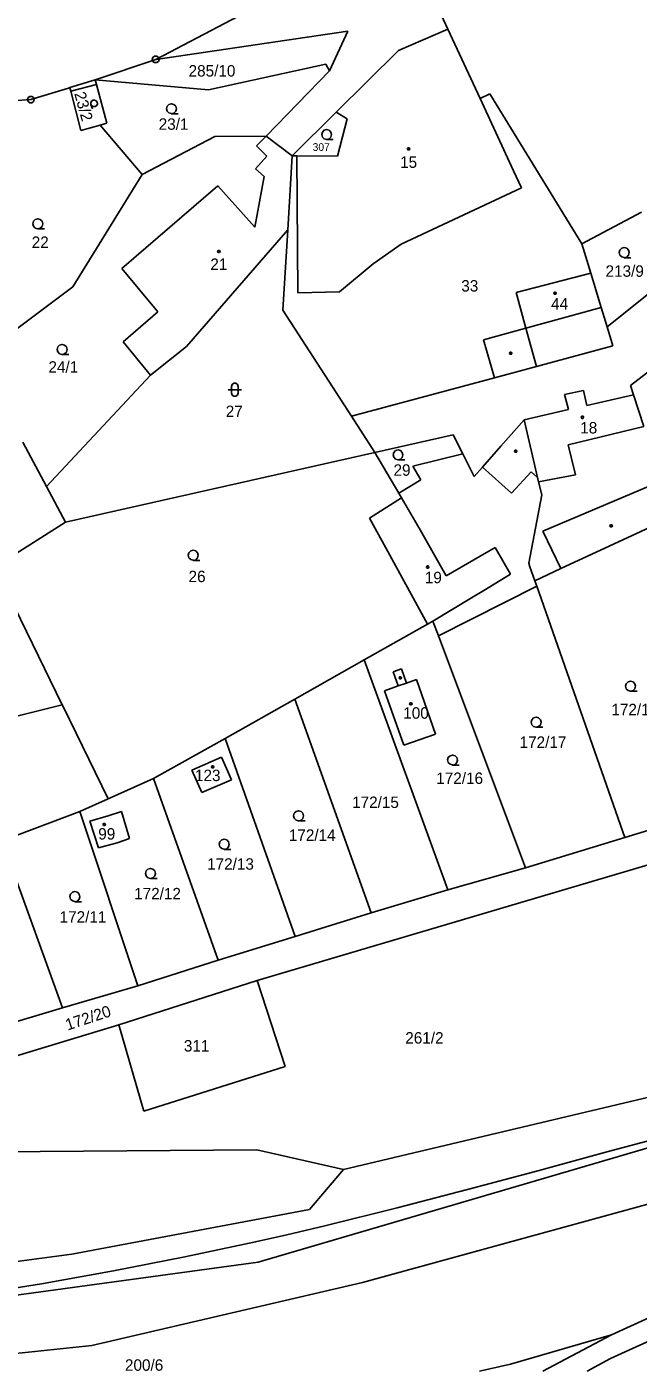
# Model space of a CAD drawing. Extents: x -779723 to -777378, y -1011169 to -1009297.
# Drawn here: x -779077.2 to -778986.4, y -1010479.3 to -1010279.6 of the extents above; entities that cross this region are included whole.
import ezdxf

# ---------------------------------------------------------------- set-up
doc = ezdxf.new("R2010")
doc.units = 0
for name, color, linetype in [('Default', 7, 'Continuous'), ('KN_HRANICE', 7, 'Continuous'), ('KN_KULTURY', 7, 'Continuous'), ('KN_PARCELY', 7, 'Continuous'), ('KN_SLUCKY', 7, 'Continuous'), ('KN_VEDENI', 7, 'Continuous'), ('Železniční svršek', 7, 'Continuous')]:
    doc.layers.add(name, color=color, linetype=linetype)

# ---------------------------------------------------------------- blocks, each defined once
blk = doc.blocks.new('304')
at = {"layer": 'Default'}
blk.add_lwpolyline([(0, 0), (-0.38, 0.1), (-0.65, 0.37), (-0.75, 0.74), (-0.65, 1.11), (-0.38, 1.38), (-0.01, 1.48), (0.36, 1.38), (0.63, 1.11), (0.73, 0.73), (0.63, 0.35), (0.36, 0.08), (-0.02, -0.02), (0.98, -0.02)], dxfattribs=at)
blk = doc.blocks.new('316')
at = {"layer": 'Default'}
for points in [[(-1, 1), (0.27, 1), (1, 1)], [(-0.5, 1.5), (-0.4, 1.79), (-0.15, 1.97), (0.16, 1.97), (0.41, 1.79), (0.51, 1.5), (0.51, 0.5), (0.41, 0.21), (0.16, 0.03), (-0.15, 0.03), (-0.4, 0.21), (-0.5, 0.5), (-0.5, 1.5)]]:
    blk.add_lwpolyline(points, dxfattribs=at)
blk = doc.blocks.new('NAHRADNI_SYMBOL')
at = {"layer": 'Default'}
blk.add_lwpolyline([(0.09, 0.15), (0.18, 0), (0.09, -0.15), (-0.09, -0.15), (-0.18, 0), (-0.09, 0.15), (0.09, 0.15)], dxfattribs=at)
blk = doc.blocks.new('402')
at = {"layer": 'Default'}
blk.add_lwpolyline([(0.09, 0.15), (0.18, 0), (0.09, -0.15), (-0.09, -0.15), (-0.18, 0), (-0.09, 0.15), (0.09, 0.15)], dxfattribs=at)
blk = doc.blocks.new('105')
at = {"layer": 'Default'}
blk.add_line((-0.12, 0), (0.12, 0), dxfattribs=at)
blk.add_lwpolyline([(0.15, 0.48), (0.4, 0.3), (0.5, 0.01), (0.4, -0.28), (0.15, -0.46), (-0.16, -0.46), (-0.41, -0.28), (-0.51, 0.01), (-0.41, 0.3), (-0.16, 0.48), (0.15, 0.48)], dxfattribs=at)

msp = doc.modelspace()

# ---------------------------------------------------------------- linework, layer by layer
at = {"layer": 'KN_HRANICE'}
for p, q in [((-779026.78, -1010253.95), (-779014.69, -1010279.95)), ((-779058.07, -1010284.48), (-779040.66, -1010275.32)), ((-779029.51, -1010280.26), (-779058.07, -1010284.48)), ((-779032.26, -1010286.16), (-779029.51, -1010280.26)), ((-779022.02, -1010283.13), (-779014.69, -1010279.95)), ((-779014.69, -1010279.95), (-779009.89, -1010290.29)), ((-779022.02, -1010283.13), (-779031.26, -1010292.31)), ((-779067.08, -1010287.5), (-779058.07, -1010284.48)), ((-779050.21, -1010289), (-779032.82, -1010285.16)), ((-779032.26, -1010286.16), (-779032.82, -1010285.16)), ((-779041.67, -1010295.86), (-779032.26, -1010286.16)), ((-779071.05, -1010288.72), (-779076.63, -1010290.43)), ((-779070.83, -1010288.65), (-779071.05, -1010288.72)), ((-779067.08, -1010287.5), (-779070.83, -1010288.65)), ((-779070.83, -1010288.65), (-779070.69, -1010289.16)), ((-779069.19, -1010295.01), (-779070.69, -1010289.16)), ((-779066.89, -1010288.17), (-779067.08, -1010287.5)), ((-779067.08, -1010287.5), (-779050.21, -1010289)), ((-779065.31, -1010293.92), (-779066.89, -1010288.17)), ((-779079.33, -1010290.64), (-779076.63, -1010290.43)), ((-779009.89, -1010290.29), (-779008.43, -1010289.59)), ((-779009.89, -1010290.29), (-779004.9, -1010301.02)), ((-778994.79, -1010311.83), (-779008.43, -1010289.59)), ((-779031.26, -1010292.31), (-779037.78, -1010298.79)), ((-779031.26, -1010292.31), (-779029.63, -1010293.31)), ((-779031.09, -1010298.84), (-779029.63, -1010293.31)), ((-779066.34, -1010294.21), (-779069.19, -1010295.01)), ((-779065.31, -1010293.92), (-779066.34, -1010294.21)), ((-779066.34, -1010294.21), (-779060.06, -1010301.54)), ((-779060.06, -1010301.54), (-779049.3, -1010295.9)), ((-779049.3, -1010295.9), (-779041.67, -1010295.86)), ((-779043.09, -1010297.32), (-779041.67, -1010295.86)), ((-779043.09, -1010297.32), (-779041.55, -1010298.82)), ((-779041.67, -1010295.86), (-779037.78, -1010298.79)), ((-779043.27, -1010300.7), (-779041.55, -1010298.82)), ((-779037.78, -1010298.79), (-779038.46, -1010309.75)), ((-779037.78, -1010298.79), (-779037.1, -1010298.8)), ((-779037.1, -1010298.8), (-779031.09, -1010298.84)), ((-779037.1, -1010298.8), (-779036.94, -1010319.12)), ((-779043.27, -1010300.7), (-779041.95, -1010301.84)), ((-779004.9, -1010301.02), (-779003.74, -1010303.52)), ((-779060.06, -1010301.54), (-779070.4, -1010318.23)), ((-779063.1, -1010315.51), (-779048.83, -1010303.23)), ((-779043.36, -1010309.37), (-779048.83, -1010303.23)), ((-779043.36, -1010309.37), (-779041.95, -1010301.84)), ((-779021.61, -1010311.89), (-779003.74, -1010303.52)), ((-778994.79, -1010311.83), (-778985.9, -1010307.16)), ((-779053.49, -1010327.09), (-779038.46, -1010309.75)), ((-779038.46, -1010309.75), (-779039.2, -1010321.7)), ((-779025.76, -1010314.84), (-779021.61, -1010311.89)), ((-778994.79, -1010311.83), (-778993.45, -1010316.22)), ((-779025.76, -1010314.84), (-779030.77, -1010318.99)), ((-779063.1, -1010315.51), (-779057.77, -1010321.93)), ((-779004.53, -1010319.08), (-778993.45, -1010316.22)), ((-778993.45, -1010316.22), (-778991.89, -1010321.33)), ((-778982.17, -1010317.08), (-778991.02, -1010324.17)), ((-779095.54, -1010337.04), (-779070.4, -1010318.23)), ((-779036.94, -1010319.12), (-779030.77, -1010318.99)), ((-779004.53, -1010319.08), (-779003.07, -1010324.38)), ((-779057.77, -1010321.93), (-779062.91, -1010326.41)), ((-779028.99, -1010337.46), (-779039.2, -1010321.7)), ((-778991.89, -1010321.33), (-778991.02, -1010324.17)), ((-779009.39, -1010326.11), (-779003.07, -1010324.38)), ((-778991.02, -1010324.17), (-778990.15, -1010327.02)), ((-779062.91, -1010326.41), (-779058.85, -1010331.38)), ((-779058.85, -1010331.38), (-779053.49, -1010327.09)), ((-779009.39, -1010326.11), (-779007.73, -1010331.75)), ((-779001.5, -1010330.08), (-778990.15, -1010327.02)), ((-779007.73, -1010331.75), (-779001.5, -1010330.08)), ((-778987.54, -1010332.88), (-778983.88, -1010330.06)), ((-779058.85, -1010331.38), (-779074.32, -1010347.9)), ((-779028.99, -1010337.46), (-779007.73, -1010331.75)), ((-778987.54, -1010332.88), (-778987.09, -1010334.27)), ((-778997.34, -1010334.21), (-778994.52, -1010333.62)), ((-778997.34, -1010334.21), (-778996.76, -1010336.48)), ((-778994.52, -1010333.62), (-778994.02, -1010335.85)), ((-778994.02, -1010335.85), (-778987.09, -1010334.27)), ((-779003.36, -1010337.99), (-778996.76, -1010336.48)), ((-779025.5, -1010342.84), (-779028.99, -1010337.46)), ((-779006.8, -1010341.91), (-779003.36, -1010337.99)), ((-779003.36, -1010337.99), (-779001.36, -1010346.54)), ((-779025.5, -1010342.84), (-779013.91, -1010340.22)), ((-779013.91, -1010340.22), (-779012.47, -1010343.06)), ((-779077.83, -1010341.29), (-779074.32, -1010347.9)), ((-779071.49, -1010353.21), (-779025.5, -1010342.84)), ((-779025.5, -1010342.84), (-779021.98, -1010348.86)), ((-779019.86, -1010344.89), (-779012.47, -1010343.06)), ((-779012.47, -1010343.06), (-779010.76, -1010346.43)), ((-779009.52, -1010345.02), (-779006.8, -1010341.91)), ((-779019.86, -1010344.89), (-779018.7, -1010346.92)), ((-779010.76, -1010346.43), (-779009.52, -1010345.02)), ((-779021.98, -1010348.86), (-779018.7, -1010346.92)), ((-779001.36, -1010346.54), (-779001.2, -1010347.2)), ((-779001.2, -1010347.2), (-779000.74, -1010349.14)), ((-779074.32, -1010347.9), (-779071.49, -1010353.21)), ((-779021.98, -1010348.86), (-779021.56, -1010349.58)), ((-779001.87, -1010355.1), (-779000.74, -1010349.14)), ((-779026.3, -1010352.61), (-779021.56, -1010349.58)), ((-779071.49, -1010353.21), (-779078.82, -1010357.83)), ((-779023.89, -1010357.02), (-779026.3, -1010352.61)), ((-778997.87, -1010360.08), (-778982.04, -1010352.73)), ((-779001.87, -1010355.1), (-779002.67, -1010359.29)), ((-779023.89, -1010357.02), (-779017.69, -1010368.36)), ((-779071.95, -1010380.31), (-779081.96, -1010359.81)), ((-779002.67, -1010359.29), (-779002.49, -1010359.8)), ((-779002.49, -1010359.8), (-779001.76, -1010361.88)), ((-779001.76, -1010361.88), (-778997.87, -1010360.08)), ((-779016.08, -1010370.08), (-779001.48, -1010362.68)), ((-779001.48, -1010362.68), (-779001.76, -1010361.88)), ((-778988.37, -1010400.03), (-779001.48, -1010362.68)), ((-779027.09, -1010373.66), (-779017.69, -1010368.36)), ((-779017.69, -1010368.36), (-779016.89, -1010367.91)), ((-779016.89, -1010367.91), (-779016.08, -1010370.08)), ((-779016.08, -1010370.08), (-779003.14, -1010404.53)), ((-779037.39, -1010379.46), (-779027.09, -1010373.66)), ((-779027.09, -1010373.66), (-779014.66, -1010407.79)), ((-779022.8, -1010375.42), (-779021.54, -1010374.98)), ((-779021.54, -1010374.98), (-779020.82, -1010377.08)), ((-779022.06, -1010377.52), (-779022.8, -1010375.42)), ((-779020.82, -1010377.08), (-779019.35, -1010376.56)), ((-779016.52, -1010384.66), (-779019.35, -1010376.56)), ((-779024.08, -1010378.22), (-779022.06, -1010377.52)), ((-779024.08, -1010378.22), (-779021.2, -1010386.31)), ((-779098.22, -1010386.86), (-779071.95, -1010380.31)), ((-779071.81, -1010380.59), (-779071.95, -1010380.31)), ((-779065.12, -1010394.29), (-779071.81, -1010380.59)), ((-779047.78, -1010385.31), (-779037.39, -1010379.46)), ((-779026.05, -1010411.22), (-779037.39, -1010379.46)), ((-779021.2, -1010386.31), (-779016.52, -1010384.66)), ((-779058.38, -1010391.28), (-779047.78, -1010385.31)), ((-779047.78, -1010385.31), (-779037.35, -1010414.74)), ((-779052.71, -1010390), (-779048.3, -1010388.08)), ((-779048.3, -1010388.08), (-779046.83, -1010391.44)), ((-779051.24, -1010393.33), (-779052.71, -1010390)), ((-779065.12, -1010394.29), (-779058.38, -1010391.28)), ((-779048.8, -1010418.22), (-779058.38, -1010391.28)), ((-779046.83, -1010391.44), (-779051.24, -1010393.33)), ((-779069.32, -1010396.17), (-779065.12, -1010394.29)), ((-779069.32, -1010396.17), (-779080.88, -1010400.54)), ((-779069.32, -1010396.17), (-779060.72, -1010422.04)), ((-779067.84, -1010397.62), (-779065.12, -1010396.78)), ((-779065.12, -1010396.78), (-779063.17, -1010396.18)), ((-779061.97, -1010400.17), (-779063.17, -1010396.18)), ((-778958.54, -1010396.31), (-779043.02, -1010421.24)), ((-778988.37, -1010400.03), (-778974.46, -1010395.73)), ((-779067.84, -1010397.62), (-779066.59, -1010401.56)), ((-779071.93, -1010425.3), (-779080.88, -1010400.54)), ((-779066.59, -1010401.56), (-779063.82, -1010400.81)), ((-779063.82, -1010400.81), (-779061.97, -1010400.17)), ((-779003.14, -1010404.53), (-778988.37, -1010400.03)), ((-779014.66, -1010407.79), (-779003.14, -1010404.53)), ((-779026.05, -1010411.22), (-779014.66, -1010407.79)), ((-779037.35, -1010414.74), (-779026.05, -1010411.22)), ((-779048.8, -1010418.22), (-779037.35, -1010414.74)), ((-779060.72, -1010422.04), (-779048.8, -1010418.22)), ((-779071.93, -1010425.3), (-779060.72, -1010422.04)), ((-779043.02, -1010421.24), (-779063.54, -1010427.85)), ((-779038.86, -1010434.01), (-779043.02, -1010421.24)), ((-779083.42, -1010428.77), (-779071.93, -1010425.3)), ((-779063.54, -1010427.85), (-779168.06, -1010459.43)), ((-779063.54, -1010427.85), (-779059.85, -1010440.67)), ((-779059.85, -1010440.67), (-779038.86, -1010434.01)), ((-779030.17, -1010449.35), (-778970.59, -1010435.19)), ((-779027.37, -1010466.13), (-778950.06, -1010444.91)), ((-779043.03, -1010446.43), (-779084.08, -1010446.73)), ((-779043.03, -1010446.43), (-779030.17, -1010449.35)), ((-779035.24, -1010455.28), (-779030.17, -1010449.35)), ((-778990.37, -1010473.89), (-778946.9, -1010453.97)), ((-779070.54, -1010461.9), (-779035.24, -1010455.28)), ((-778945.86, -1010456.94), (-778990.5, -1010477.42)), ((-779127.38, -1010469.51), (-779070.54, -1010461.9)), ((-779067.56, -1010475.45), (-779027.37, -1010466.13)), ((-779005.39, -1010478.26), (-778990.37, -1010473.89)), ((-778990.37, -1010473.89), (-779000.59, -1010479.27)), ((-779103.26, -1010479.27), (-779067.56, -1010475.45)), ((-779009.99, -1010479.27), (-779005.39, -1010478.26)), ((-778990.5, -1010477.42), (-778994, -1010479.27))]:
    msp.add_line(p, q, dxfattribs=at)
at = {"layer": 'KN_SLUCKY'}
for p, q in [((-779070.69, -1010289.16), (-779066.89, -1010288.17)), ((-779003.07, -1010324.38), (-778991.89, -1010321.33)), ((-779003.07, -1010324.38), (-779001.5, -1010330.08)), ((-778987.09, -1010334.27), (-778985.56, -1010339)), ((-778996.79, -1010341.72), (-778985.56, -1010339)), ((-778996.79, -1010341.72), (-778995.73, -1010346.15)), ((-779009.52, -1010345.02), (-779005.2, -1010348.89)), ((-779005.2, -1010348.89), (-779002.31, -1010345.73)), ((-779002.31, -1010345.73), (-779001.36, -1010346.54)), ((-779001.2, -1010347.2), (-778995.73, -1010346.15)), ((-779000.55, -1010354.53), (-778983.47, -1010347.31)), ((-779021.56, -1010349.58), (-779018.79, -1010354.32)), ((-779018.79, -1010354.32), (-779014.92, -1010361.14)), ((-778997.87, -1010360.08), (-779000.55, -1010354.53)), ((-779014.92, -1010361.14), (-779007.64, -1010356.95)), ((-779007.64, -1010356.95), (-779005.36, -1010360.92)), ((-779009.32, -1010363.32), (-779005.36, -1010360.92)), ((-779016.89, -1010367.91), (-779011.17, -1010364.44)), ((-779011.17, -1010364.44), (-779009.32, -1010363.32)), ((-779022.06, -1010377.52), (-779020.82, -1010377.08))]:
    msp.add_line(p, q, dxfattribs=at)
at = {"layer": 'KN_VEDENI'}
for p, q in [((-779042.85, -1010463.08), (-778940.99, -1010433.26)), ((-779130.44, -1010475.03), (-779042.85, -1010463.08))]:
    msp.add_line(p, q, dxfattribs=at)
at = {"layer": 'Železniční svršek'}
for points in [[(-778980.43, -1010443.86), (-778990.86, -1010446.68)], [(-778990.86, -1010446.68), (-779001.31, -1010449.51)], [(-779001.31, -1010449.51), (-779011.77, -1010452.29)], [(-779011.77, -1010452.29), (-779022.21, -1010455.01)], [(-779022.22, -1010455.01), (-779032.96, -1010457.68)], [(-779038.58, -1010459.01), (-779043.23, -1010460.07)], [(-779032.97, -1010457.68), (-779038.58, -1010459.01)], [(-779043.24, -1010460.07), (-779053.74, -1010462.32)], [(-779053.76, -1010462.32), (-779064.35, -1010464.39)], [(-779064.36, -1010464.39), (-779075.03, -1010466.3)], [(-779075.05, -1010466.31), (-779086.32, -1010468.1)]]:
    msp.add_lwpolyline(points, dxfattribs=at)
for centre, start, end in [((-778990.6, -1010447.65), 105.1366, 105.1456), ((-779001.57, -1010448.55), 284.8902, 285.1456), ((-779012.02, -1010451.33), 284.599, 284.8902), ((-779022.46, -1010454.04), 283.9397, 284.599), ((-779038.81, -1010458.03), 282.9011, 283.2752), ((-779033.2, -1010456.71), 283.2752, 283.9397), ((-779043.45, -1010459.1), 282.0549, 282.9011), ((-779053.95, -1010461.34), 281.0645, 282.0549), ((-779064.54, -1010463.41), 280.149, 281.0645), ((-779075.2, -1010465.32), 279.019, 280.149)]:
    msp.add_arc(centre, 1, start, end, dxfattribs=at)

# ---------------------------------------------------------------- block references
at = {"layer": 'KN_KULTURY', "xscale": 0.67, "yscale": 0.6699999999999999, "rotation": -67.61963700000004}
msp.add_blockref('304', (-779067.69, -1010291.18), dxfattribs=at)
at = {"layer": 'KN_KULTURY'}
for name, p in [('304', (-779055.72, -1010292.52)), ('304', (-779032.67, -1010296.36)), ('NAHRADNI_SYMBOL', (-779020.51, -1010297.75)), ('304', (-779075.59, -1010309.61)), ('NAHRADNI_SYMBOL', (-779048.69, -1010313)), ('304', (-778988.47, -1010313.89)), ('402', (-778998.76, -1010319.2)), ('304', (-779071.97, -1010328.28)), ('402', (-779005.34, -1010328.1)), ('316', (-779046.31, -1010334.53)), ('402', (-778994.69, -1010337.62)), ('304', (-779022.07, -1010343.93)), ('402', (-779004.6, -1010342.65)), ('402', (-778990.42, -1010353.75)), ('304', (-779052.49, -1010358.84)), ('402', (-779017.68, -1010359.85)), ('402', (-779021.73, -1010376.29)), ('304', (-778987.53, -1010378.29)), ('402', (-779020.18, -1010380.17)), ('304', (-779001.56, -1010383.64)), ('304', (-779013.97, -1010389.25)), ('402', (-779049.61, -1010389.53)), ('304', (-779036.84, -1010397.54)), ('402', (-779065.72, -1010398.09)), ('304', (-779047.89, -1010401.77)), ('304', (-779058.85, -1010406.09)), ('304', (-779070.07, -1010409.54))]:
    msp.add_blockref(name, p, dxfattribs=at)
at = {"layer": 'KN_PARCELY'}
for p in [(-779058.07, -1010284.48), (-779076.63, -1010290.43)]:
    msp.add_blockref('105', p, dxfattribs=at)

# ---------------------------------------------------------------- texts
for s, height, p in [('285/10', 1.7, (-779053.19, -1010287.01)), ('23/1', 1.7, (-779057.63, -1010294.92)), ('307', 1.14, (-779034.76, -1010298.05)), ('15', 1.7, (-779021.77, -1010300.57)), ('22', 1.7, (-779076.49, -1010312.46)), ('21', 1.7, (-779049.96, -1010315.73)), ('213/9', 1.7, (-778991.25, -1010316.75)), ('33', 1.7, (-779012.68, -1010318.94)), ('44', 1.7, (-778999.34, -1010321.61)), ('24/1', 1.7, (-779074.01, -1010330.99)), ('27', 1.7, (-779047.67, -1010337.58)), ('18', 1.7, (-778995.01, -1010340.02)), ('29', 1.7, (-779022.75, -1010346.3)), ('26', 1.7, (-779053.19, -1010362.1)), ('19', 1.7, (-779018.1, -1010362.26)), ('100', 1.7, (-779021.3, -1010382.38)), ('172/18', 1.7, (-778990.39, -1010381.87)), ('172/17', 1.7, (-779004.02, -1010386.71)), ('123', 1.7, (-779052.24, -1010391.65)), ('172/16', 1.7, (-779016.4, -1010392.07)), ('172/15', 1.7, (-779028.9, -1010395.64)), ('99', 1.7, (-779066.61, -1010400.33)), ('172/14', 1.7, (-779038.3, -1010400.52)), ('172/13', 1.7, (-779050.44, -1010404.81)), ('172/12', 1.7, (-779061.28, -1010409.21)), ('172/11', 1.7, (-779072.35, -1010412.67)), ('261/2', 1.7, (-779021, -1010430.63)), ('311', 1.7, (-779053.89, -1010431.81)), ('200/6', 1.7, (-779062.64, -1010479.22))]:
    msp.add_text(s, height=height, dxfattribs=at).set_placement(p)
for s, rotation, p in [('23/2', 285.448, (-779070.19, -1010289.53)), ('172/20', 18.277, (-779071.16, -1010428.7))]:
    msp.add_text(s, height=1.7, rotation=rotation, dxfattribs=at).set_placement(p)

doc.saveas('drawing.dxf')
